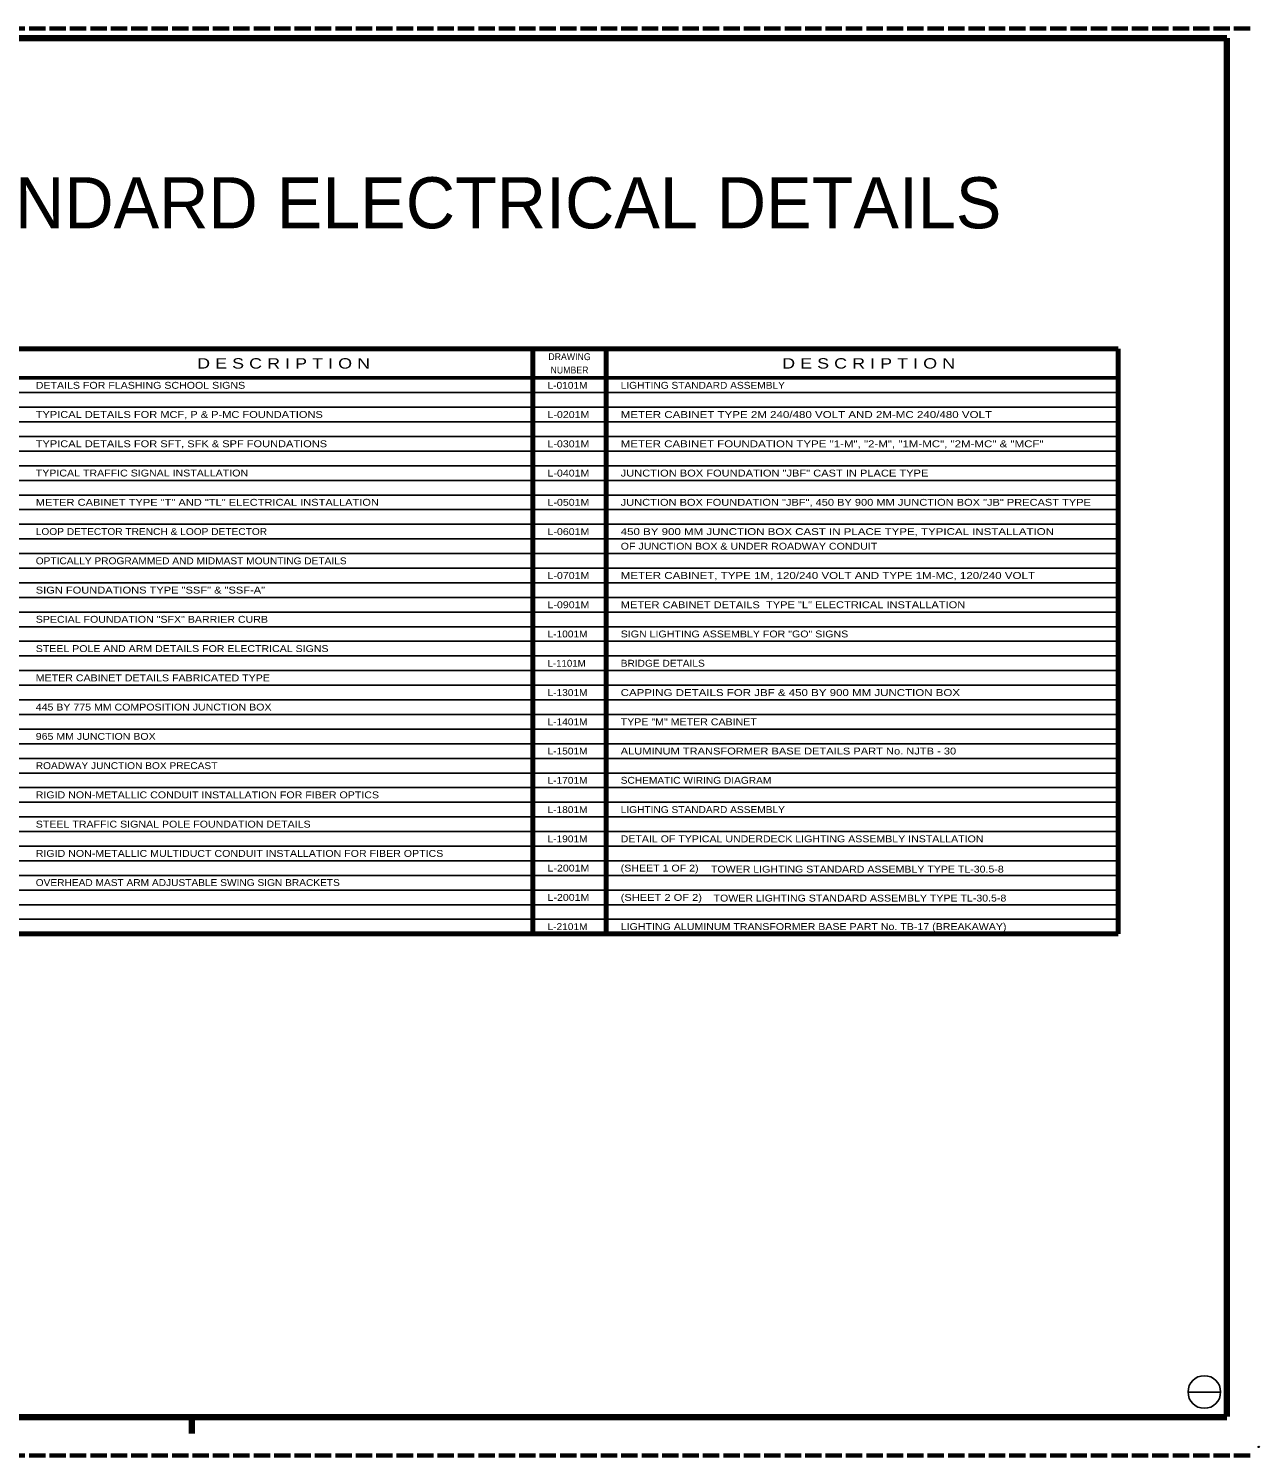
# Model space of a CAD drawing. Extents: x 312912 to 313215, y 317800 to 318182.
# Drawn here: x 313043.7 to 313188.4, y 317799.5 to 317967.2 of the extents above; entities that cross this region are included whole.
import ezdxf
from ezdxf.enums import TextEntityAlignment as Align

# ---------------------------------------------------------------- set-up
doc = ezdxf.new("R2010")
doc.units = 0
doc.header["$LTSCALE"] = 0.32
doc.header["$PDMODE"] = 32
doc.header["$PDSIZE"] = 0.16
doc.linetypes.add('LONG_DASHED', pattern=[7.5, 6, -1.5])
for name, color, linetype, lineweight in [('1', 7, 'Continuous', 13), ('10', 7, 'Continuous', 25), ('63', 7, 'LONG_DASHED', 60)]:
    doc.layers.add(name, color=color, linetype=linetype, lineweight=lineweight)

msp = doc.modelspace()

# ---------------------------------------------------------------- linework, layer by layer
at = {"layer": '1', "lineweight": 158}
for p, q in [((313184.5648, 317804.0884), (313184.5648, 317966.0284)), ((312952.0648, 317804.0284), (313184.5648, 317804.0284)), ((313062.9148, 317802.1084), (313062.9148, 317804.0284))]:
    msp.add_line(p, q, dxfattribs=at)
at = {"layer": '1', "lineweight": 70}
for p, q in [((312962.2023, 317929.5485), (313171.7688, 317929.5485)), ((313103.0133, 317929.5485), (313103.0133, 317860.8013)), ((313111.6098, 317929.5485), (313111.6098, 317860.8013)), ((313171.7688, 317929.5485), (313171.7688, 317860.8013)), ((313034.266, 317860.8013), (313103.0133, 317860.8013)), ((313103.0133, 317860.8013), (313171.7688, 317860.8013))]:
    msp.add_line(p, q, dxfattribs=at)
at = {"layer": '1', "lineweight": 25}
for p, q in [((313034.266, 317924.3923), (313103.0133, 317924.3923)), ((313103.0133, 317924.3923), (313171.7688, 317924.3923)), ((313034.266, 317922.6763), (313103.0133, 317922.6763)), ((313103.0133, 317922.6763), (313171.7688, 317922.6763)), ((313034.266, 317920.9603), (313103.0133, 317920.9603)), ((313103.0133, 317920.9603), (313171.7688, 317920.9603)), ((313034.266, 317919.236), (313103.0133, 317919.236)), ((313103.0133, 317919.236), (313171.7688, 317919.236)), ((313034.266, 317917.52), (313103.0133, 317917.52)), ((313103.0133, 317917.52), (313171.7688, 317917.52)), ((313034.266, 317915.804), (313103.0133, 317915.804)), ((313103.0133, 317915.804), (313171.7688, 317915.804)), ((313034.266, 317914.0798), (313103.0133, 317914.0798)), ((313103.0133, 317914.0798), (313171.7688, 317914.0798)), ((313034.266, 317912.3638), (313103.0133, 317912.3638)), ((313103.0133, 317912.3638), (313171.7688, 317912.3638)), ((313034.266, 317910.6478), (313103.0133, 317910.6478)), ((313103.0133, 317910.6478), (313171.7688, 317910.6478)), ((313034.266, 317908.9235), (313103.0133, 317908.9235)), ((313103.0133, 317908.9235), (313171.7688, 317908.9235)), ((313034.266, 317907.2075), (313103.0133, 317907.2075)), ((313103.0133, 317907.2075), (313171.7688, 317907.2075)), ((313034.266, 317905.4915), (313103.0133, 317905.4915)), ((313103.0133, 317905.4915), (313171.7688, 317905.4915)), ((313034.266, 317903.7673), (313103.0133, 317903.7673)), ((313103.0133, 317903.7673), (313171.7688, 317903.7673)), ((313034.266, 317902.0513), (313103.0133, 317902.0513)), ((313103.0133, 317902.0513), (313171.7688, 317902.0513)), ((313034.266, 317900.3353), (313103.0133, 317900.3353)), ((313103.0133, 317900.3353), (313171.7688, 317900.3353)), ((313034.266, 317898.611), (313103.0133, 317898.611)), ((313103.0133, 317898.611), (313171.7688, 317898.611)), ((313034.266, 317896.895), (313103.0133, 317896.895)), ((313103.0133, 317896.895), (313171.7688, 317896.895)), ((313034.266, 317895.179), (313103.0133, 317895.179)), ((313103.0133, 317895.179), (313171.7688, 317895.179)), ((313034.266, 317893.4548), (313103.0133, 317893.4548)), ((313103.0133, 317893.4548), (313171.7688, 317893.4548)), ((313034.266, 317891.7388), (313103.0133, 317891.7388)), ((313103.0133, 317891.7388), (313171.7688, 317891.7388)), ((313034.266, 317890.0145), (313103.0133, 317890.0145)), ((313103.0133, 317890.0145), (313171.7688, 317890.0145)), ((313034.266, 317888.2985), (313103.0133, 317888.2985)), ((313103.0133, 317888.2985), (313171.7688, 317888.2985)), ((313034.266, 317886.5825), (313103.0133, 317886.5825)), ((313103.0133, 317886.5825), (313171.7688, 317886.5825)), ((313034.266, 317884.8583), (313103.0133, 317884.8583)), ((313103.0133, 317884.8583), (313171.7688, 317884.8583)), ((313034.266, 317883.1423), (313103.0133, 317883.1423)), ((313103.0133, 317883.1423), (313171.7688, 317883.1423)), ((313034.266, 317881.4263), (313103.0133, 317881.4263)), ((313103.0133, 317881.4263), (313171.7688, 317881.4263)), ((313034.266, 317879.702), (313103.0133, 317879.702)), ((313103.0133, 317879.702), (313171.7688, 317879.702)), ((313034.266, 317877.986), (313103.0133, 317877.986)), ((313103.0133, 317877.986), (313171.7688, 317877.986)), ((313034.266, 317876.27), (313103.0133, 317876.27)), ((313103.0133, 317876.27), (313171.7688, 317876.27)), ((313034.266, 317874.5458), (313103.0133, 317874.5458)), ((313103.0133, 317874.5458), (313171.7688, 317874.5458)), ((313034.266, 317872.8298), (313103.0133, 317872.8298)), ((313103.0133, 317872.8298), (313171.7688, 317872.8298)), ((313034.266, 317871.1138), (313103.0133, 317871.1138)), ((313103.0133, 317871.1138), (313171.7688, 317871.1138)), ((313034.266, 317869.3895), (313103.0133, 317869.3895)), ((313103.0133, 317869.3895), (313171.7688, 317869.3895)), ((313034.266, 317867.6735), (313103.0133, 317867.6735)), ((313103.0133, 317867.6735), (313171.7688, 317867.6735)), ((313034.266, 317865.9575), (313103.0133, 317865.9575)), ((313103.0133, 317865.9575), (313171.7688, 317865.9575)), ((313034.266, 317864.2333), (313103.0133, 317864.2333)), ((313103.0133, 317864.2333), (313171.7688, 317864.2333)), ((313034.266, 317862.5173), (313103.0133, 317862.5173)), ((313103.0133, 317862.5173), (313171.7688, 317862.5173))]:
    msp.add_line(p, q, dxfattribs=at)
at = {"layer": '1', "lineweight": 158}
msp.add_lwpolyline([(312952.0648, 317804.0884), (312952.0648, 317966.0284), (313184.5648, 317966.0284)], dxfattribs=at)
at = {"layer": '1', "lineweight": 53}
msp.add_lwpolyline([(312962.2023, 317926.1165), (313034.266, 317926.1165), (313103.0133, 317926.1165), (313171.7688, 317926.1165)], dxfattribs=at)
at = {"layer": '1'}
msp.add_point((313188.3148, 317800.5284), dxfattribs=at)
at = {"layer": '10'}
msp.add_line((313180.0032, 317806.9697), (313183.8442, 317806.9697), dxfattribs=at)
msp.add_line((313180.0032, 317806.9697), (313183.8442, 317806.9697), dxfattribs=at)
msp.add_line((313180.0032, 317806.9697), (313183.8442, 317806.9697), dxfattribs=at)
msp.add_circle((313181.9142, 317806.9843), 1.9159, dxfattribs=at)
at = {"layer": '63'}
for p, q in [((313187.3148, 317967.1684), (312919.0908, 317967.1684)), ((313187.3148, 317799.5284), (312919.0908, 317799.5284))]:
    msp.add_line(p, q, dxfattribs=at)

# ---------------------------------------------------------------- texts
at = {"layer": '1'}
msp.add_text('INDEX FOR STANDARD ELECTRICAL DETAILS', height=6, dxfattribs=at).set_placement((313069.3404, 317943.7003), align=Align.CENTER)
for s, height, width, p in [('D E S C R I P T I O N', 1.217, 1.3, (313073.7061, 317927.222)), ('DRAWING', 0.8113, 0.95, (313107.3062, 317928.212)), ('D E S C R I P T I O N', 1.217, 1.3, (313142.4616, 317927.222)), ('NUMBER', 0.8113, 0.95, (313107.3075, 317926.6445))]:
    msp.add_text(s, height=height, dxfattribs=dict(at, width=width)).set_placement(p, align=Align.CENTER)
for s, height, width, p in [('DETAILS FOR FLASHING SCHOOL SIGNS', 0.8113, 1.15, (313044.5785, 317924.846)), ('L-0101M', 0.8085, 1.1, (313104.7293, 317924.846)), ('LIGHTING STANDARD ASSEMBLY', 0.8113, 1.1, (313113.3258, 317924.846)), ('TYPICAL DETAILS FOR MCF, P & P-MC FOUNDATIONS', 0.8085, 1.2, (313044.5785, 317921.4223)), ('L-0201M', 0.8085, 1.15, (313104.7293, 317921.414)), ('METER CABINET TYPE 2M 240/480 VOLT AND 2M-MC 240/480 VOLT', 0.8113, 1.25, (313113.3258, 317921.414)), ('TYPICAL DETAILS FOR SFT, SFK & SPF FOUNDATIONS', 0.8085, 1.2, (313044.5785, 317917.982)), ('L-0301M', 0.8085, 1.15, (313104.7293, 317917.9738)), ('METER CABINET FOUNDATION TYPE "1-M", "2-M", "1M-MC", "2M-MC" & "MCF"', 0.8085, 1.25, (313113.3258, 317917.9738)), ('TYPICAL TRAFFIC SIGNAL INSTALLATION', 0.8113, 1.15, (313044.5785, 317914.5418)), ('L-0401M', 0.8085, 1.15, (313104.7293, 317914.5335)), ('JUNCTION BOX FOUNDATION "JBF" CAST IN PLACE TYPE', 0.8113, 1.2, (313113.3258, 317914.5335)), ('METER CABINET TYPE "T" AND "TL" ELECTRICAL INSTALLATION', 0.8113, 1.2, (313044.5785, 317911.1015)), ('L-0501M', 0.8085, 1.15, (313104.7293, 317911.1015)), ('JUNCTION BOX FOUNDATION "JBF", 450 BY 900 MM JUNCTION BOX "JB" PRECAST TYPE', 0.8085, 1.2, (313113.3258, 317911.1015)), ('LOOP DETECTOR TRENCH & LOOP DETECTOR', 0.8113, 1.1, (313044.5785, 317907.6695)), ('L-0601M', 0.8085, 1.15, (313104.7293, 317907.6613)), ('450 BY 900 MM JUNCTION BOX CAST IN PLACE TYPE, TYPICAL INSTALLATION', 0.8085, 1.25, (313113.3258, 317907.6613)), ('OF JUNCTION BOX & UNDER ROADWAY CONDUIT', 0.8113, 1.15, (313113.3258, 317905.9453)), ('OPTICALLY PROGRAMMED AND MIDMAST MOUNTING DETAILS', 0.8113, 1.1, (313044.5785, 317904.2293)), ('L-0701M', 0.8085, 1.15, (313104.7293, 317902.505)), ('METER CABINET, TYPE 1M, 120/240 VOLT AND TYPE 1M-MC, 120/240 VOLT', 0.8113, 1.25, (313113.3258, 317902.505)), ('SIGN FOUNDATIONS TYPE "SSF" & "SSF-A"', 0.8113, 1.2, (313044.5785, 317900.789)), ('L-0901M', 0.8085, 1.15, (313104.7293, 317899.0648)), ('METER CABINET DETAILS  TYPE "L" ELECTRICAL INSTALLATION', 0.8113, 1.2, (313113.3258, 317899.0648)), ('SPECIAL FOUNDATION "SFX" BARRIER CURB', 0.8113, 1.15, (313044.5785, 317897.357)), ('L-1001M', 0.8085, 1.1, (313104.7293, 317895.6328)), ('SIGN LIGHTING ASSEMBLY FOR "GO" SIGNS', 0.8113, 1.15, (313113.3258, 317895.6328)), ('STEEL POLE AND ARM DETAILS FOR ELECTRICAL SIGNS', 0.8085, 1.15, (313044.5785, 317893.9168)), ('L-1101M', 0.8085, 1.05, (313104.7293, 317892.1925)), ('BRIDGE DETAILS', 0.8113, 1.1, (313113.3258, 317892.1925)), ('METER CABINET DETAILS FABRICATED TYPE', 0.8113, 1.15, (313044.5785, 317890.4765)), ('L-1301M', 0.8085, 1.1, (313104.7293, 317888.7523)), ('CAPPING DETAILS FOR JBF & 450 BY 900 MM JUNCTION BOX', 0.8085, 1.25, (313113.3258, 317888.7523)), ('445 BY 775 MM COMPOSITION JUNCTION BOX', 0.8085, 1.15, (313044.5785, 317887.0445)), ('L-1401M', 0.8085, 1.1, (313104.7293, 317885.312)), ('TYPE "M" METER CABINET', 0.8113, 1.15, (313113.3258, 317885.312)), ('965 MM JUNCTION BOX', 0.8085, 1.15, (313044.5785, 317883.6043)), ('L-1501M', 0.8085, 1.1, (313104.7293, 317881.88)), ('ALUMINUM TRANSFORMER BASE DETAILS PART No. NJTB - 30', 0.8113, 1.2, (313113.3258, 317881.88)), ('ROADWAY JUNCTION BOX PRECAST', 0.8113, 1.1, (313044.5785, 317880.164)), ('L-1701M', 0.8085, 1.1, (313104.7293, 317878.4398)), ('SCHEMATIC WIRING DIAGRAM', 0.8113, 1.1, (313113.3258, 317878.4398)), ('RIGID NON-METALLIC CONDUIT INSTALLATION FOR FIBER OPTICS', 0.8113, 1.15, (313044.5785, 317876.732)), ('L-1801M', 0.8085, 1.1, (313104.7293, 317874.9995)), ('LIGHTING STANDARD ASSEMBLY', 0.8113, 1.1, (313113.3258, 317874.9995)), ('STEEL TRAFFIC SIGNAL POLE FOUNDATION DETAILS', 0.8113, 1.15, (313044.5785, 317873.2918)), ('L-1901M', 0.8085, 1.1, (313104.7293, 317871.5675)), ('DETAIL OF TYPICAL UNDERDECK LIGHTING ASSEMBLY INSTALLATION', 0.8085, 1.15, (313113.3258, 317871.5675)), ('RIGID NON-METALLIC MULTIDUCT CONDUIT INSTALLATION FOR FIBER OPTICS', 0.8113, 1.15, (313044.5785, 317869.8515)), ('L-2001M', 0.8085, 1.15, (313104.7293, 317868.1273)), ('(SHEET 1 OF 2)', 0.8113, 1.15, (313113.3258, 317868.1273)), ('OVERHEAD MAST ARM ADJUSTABLE SWING SIGN BRACKETS', 0.8113, 1.1, (313044.5747, 317866.4287)), ('TOWER LIGHTING STANDARD ASSEMBLY TYPE TL-30.5-8', 0.8085, 1.15, (313123.9353, 317868.0035)), ('L-2001M', 0.8085, 1.15, (313104.7293, 317864.687)), ('(SHEET 2 OF 2)', 0.8113, 1.2, (313113.3258, 317864.687)), ('TOWER LIGHTING STANDARD ASSEMBLY TYPE TL-30.5-8', 0.8085, 1.15, (313124.2405, 317864.6045)), ('L-2101M', 0.8085, 1.1, (313104.7293, 317861.255)), ('LIGHTING ALUMINUM TRANSFORMER BASE PART No. TB-17 (BREAKAWAY)', 0.8113, 1.15, (313113.3258, 317861.255))]:
    msp.add_text(s, height=height, dxfattribs=dict(at, width=width)).set_placement(p)

doc.saveas('drawing.dxf')
